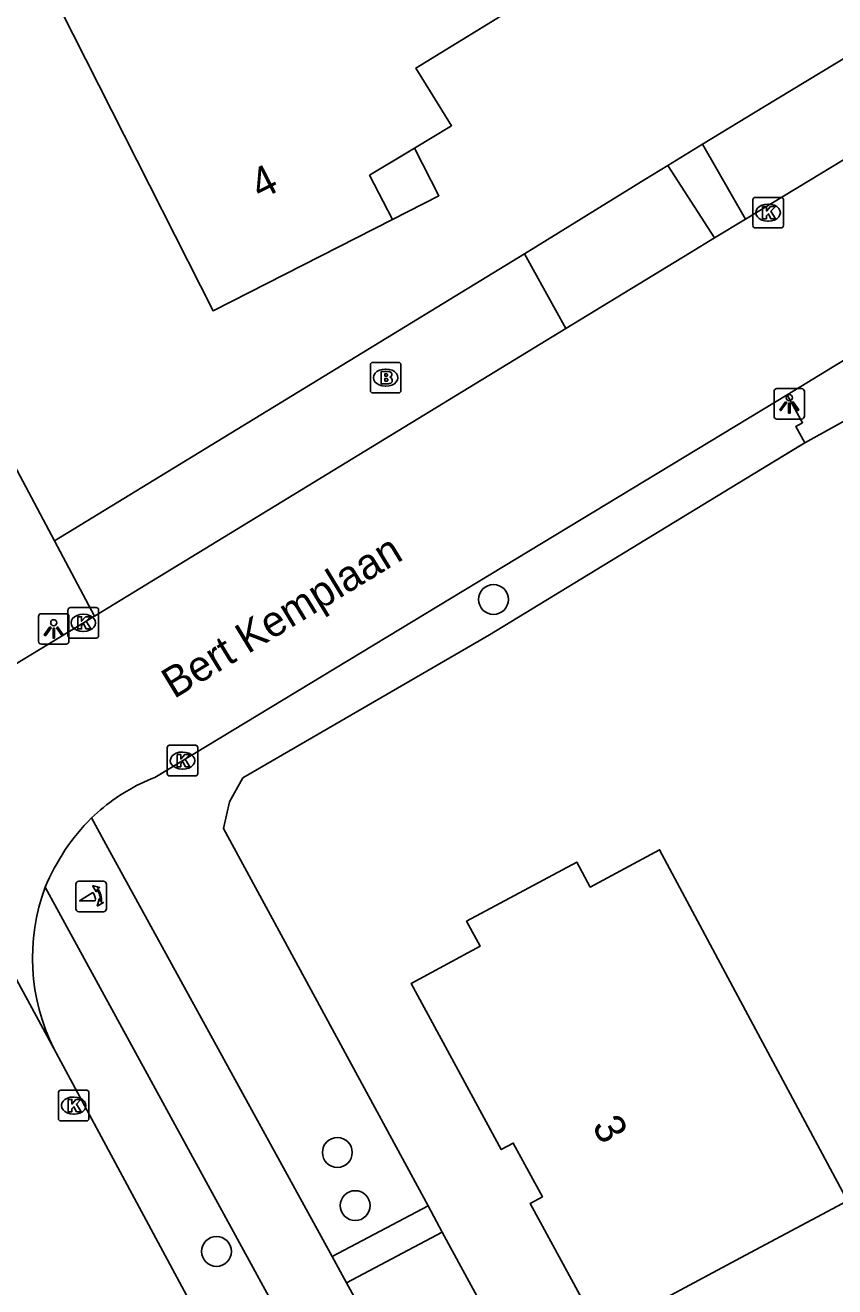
# Model space of a CAD drawing. Extents: x 157321 to 158827, y 386650 to 388532.
# Drawn here: x 157976.42 to 158002.92, y 387191.23 to 387232.53 of the extents above; entities that cross this region are included whole.
import ezdxf

# ---------------------------------------------------------------- set-up
doc = ezdxf.new("R2010")
doc.units = 0
for name, color, linetype in [('IMGEO_Boom', 7, 'Continuous'), ('IMGEO_Brandkraan', 7, 'Continuous'), ('IMGEO_Groenvoorziening', 7, 'Continuous'), ('IMGEO_Hek', 7, 'Continuous'), ('IMGEO_Kolk', 7, 'Continuous'), ('IMGEO_Lichtpunt', 7, 'Continuous'), ('IMGEO_Openbare_ruimte_label', 7, 'Continuous'), ('IMGEO_Pand', 7, 'Continuous'), ('IMGEO_Pand_nummerreeks', 7, 'Continuous'), ('IMGEO_Pand_overbouw', 7, 'Continuous'), ('IMGEO_Poller', 7, 'Continuous'), ('IMGEO_Rijbaan_lokaal_gesloten', 7, 'Continuous'), ('IMGEO_Voetpad_open', 7, 'Continuous')]:
    doc.layers.add(name, color=color, linetype=linetype)

msp = doc.modelspace()

# ---------------------------------------------------------------- linework, layer by layer
at = {"layer": 'IMGEO_Boom'}
for centre in [(157991.746, 387213.728), (157986.635, 387195.623), (157987.219, 387193.883), (157982.679, 387192.384)]:
    msp.add_circle(centre, 0.489, dxfattribs=at)
at = {"layer": 'IMGEO_Brandkraan'}
for p, q in [((157987.716, 387220.565), (157987.716, 387221.417)), ((157987.791, 387221.491), (157988.643, 387221.491)), ((157988.717, 387221.417), (157988.717, 387220.565)), ((157988.204, 387221.271), (157988.229, 387221.271)), ((157988.227, 387220.711), (157988.202, 387220.711)), ((157988.643, 387220.491), (157987.791, 387220.491))]:
    msp.add_line(p, q, dxfattribs=at)
for points in [[(157987.716, 387220.565), (157987.716, 387221.417)], [(157987.791, 387221.491), (157988.643, 387221.491)], [(157988.717, 387221.417), (157988.717, 387220.565)], [(157988.064, 387221.191), (157988.064, 387220.791), (157988.277, 387220.791)], [(157988.295, 387221.191), (157988.064, 387221.191)], [(157988.243, 387221.11), (157988.189, 387221.11), (157988.189, 387221.034)], [(157988.189, 387221.034), (157988.242, 387221.034)], [(157988.251, 387220.958), (157988.189, 387220.958), (157988.189, 387220.877)], [(157988.189, 387220.877), (157988.251, 387220.877)], [(157988.643, 387220.491), (157987.791, 387220.491)]]:
    msp.add_lwpolyline(points, dxfattribs=at)
for centre, radius, start, end in [((157987.793, 387221.415), 0.0765, 91.552, 178.448), ((157987.793, 387221.415), 0.0765, 91.552, 178.448), ((157988.641, 387221.415), 0.0765, 1.552, 88.448), ((157988.641, 387221.415), 0.0765, 1.552, 88.448), ((157988.244, 387221.072), 0.0379, 267.8285, 90.9355), ((157988.299, 387221.046), 0.145, 59.4692, 91.5367), ((157988.324, 387221.093), 0.0922, 285.5137, 58.1501), ((157988.329, 387220.901), 0.105, 301.3115, 78.989), ((157987.793, 387220.567), 0.0765, 181.552, 268.448), ((157987.793, 387220.567), 0.0765, 181.552, 268.448), ((157988.252, 387220.917), 0.0404, 269.8759, 90.5077), ((157988.283, 387221.042), 0.251, 268.6676, 293.5347), ((157988.641, 387220.567), 0.0765, 271.552, 358.448), ((157988.641, 387220.567), 0.0765, 271.552, 358.448)]:
    msp.add_arc(centre, radius, start, end, dxfattribs=at)
for centre, major_axis, ratio, start_param, end_param in [((157988.203, 387220.991), (-0.387, 0.002), 0.722429, 4.712389, 7.853982), ((157988.228, 387220.991), (-0.39, 0.002), 0.717154, 1.570796, 4.712389)]:
    msp.add_ellipse(centre, major_axis=major_axis, ratio=ratio, start_param=start_param, end_param=end_param, dxfattribs=at)
at = {"layer": 'IMGEO_Groenvoorziening'}
for points in [[(157963.282, 387242.2), (157977.374, 387215.649)], [(157997.452, 387227.935), (157998.588, 387228.631)], [(157977.374, 387215.649), (157992.758, 387225.048)], [(158001.936, 387218.855), (158000, 387217.682), (157991.613, 387212.573), (157983.543, 387207.885), (157983.105, 387207.103), (157982.905, 387206.23), (157989.606, 387193.874)], [(157977.374, 387215.649), (157978.682, 387213.184)], [(157990.07, 387193.018), (157992.639, 387188.28)]]:
    msp.add_lwpolyline(points, dxfattribs=at)
at = {"layer": 'IMGEO_Hek'}
for points in [[(158001.811, 387218.785), (158000, 387217.682)], [(158000, 387217.682), (157991.613, 387212.573)]]:
    msp.add_lwpolyline(points, dxfattribs=at)
at = {"layer": 'IMGEO_Kolk'}
for p, q in [((158000.235, 387225.966), (158000.235, 387226.818)), ((158000.31, 387226.892), (158001.162, 387226.892)), ((158001.236, 387226.818), (158001.236, 387225.966)), ((158000.723, 387226.672), (158000.748, 387226.672)), ((158000.746, 387226.112), (158000.721, 387226.112)), ((158001.162, 387225.892), (158000.31, 387225.892)), ((157977.818, 387212.538), (157977.818, 387213.39)), ((157977.893, 387213.464), (157978.745, 387213.464)), ((157978.306, 387213.244), (157978.331, 387213.244)), ((157978.819, 387213.39), (157978.819, 387212.538)), ((157978.745, 387212.464), (157977.893, 387212.464)), ((157978.329, 387212.684), (157978.304, 387212.684)), ((157981.066, 387208.027), (157981.066, 387208.879)), ((157981.141, 387208.953), (157981.993, 387208.953)), ((157981.554, 387208.733), (157981.579, 387208.733)), ((157982.067, 387208.879), (157982.067, 387208.027)), ((157981.577, 387208.173), (157981.552, 387208.173)), ((157981.993, 387207.953), (157981.141, 387207.953)), ((157977.504, 387196.732), (157977.504, 387197.584)), ((157977.579, 387197.658), (157978.431, 387197.658)), ((157977.992, 387197.438), (157978.017, 387197.438)), ((157978.505, 387197.584), (157978.505, 387196.732)), ((157978.431, 387196.658), (157977.579, 387196.658)), ((157978.015, 387196.878), (157977.99, 387196.878))]:
    msp.add_line(p, q, dxfattribs=at)
for points in [[(158000.235, 387225.966), (158000.235, 387226.818)], [(158000.31, 387226.892), (158001.162, 387226.892)], [(158001.236, 387226.818), (158001.236, 387225.966)], [(158000.556, 387226.592), (158000.679, 387226.592), (158000.679, 387226.441), (158000.809, 387226.592), (158000.973, 387226.592), (158000.827, 387226.441), (158000.98, 387226.192), (158000.828, 387226.192), (158000.743, 387226.356), (158000.679, 387226.289), (158000.679, 387226.192), (158000.556, 387226.192), (158000.556, 387226.592)], [(158001.162, 387225.892), (158000.31, 387225.892)], [(157977.818, 387212.538), (157977.818, 387213.39)], [(157977.893, 387213.464), (157978.745, 387213.464)], [(157978.139, 387213.164), (157978.262, 387213.164), (157978.262, 387213.013), (157978.392, 387213.164), (157978.556, 387213.164), (157978.41, 387213.013), (157978.563, 387212.764), (157978.411, 387212.764), (157978.326, 387212.928), (157978.262, 387212.861), (157978.262, 387212.764), (157978.139, 387212.764), (157978.139, 387213.164)], [(157978.819, 387213.39), (157978.819, 387212.538)], [(157978.745, 387212.464), (157977.893, 387212.464)], [(157981.066, 387208.027), (157981.066, 387208.879)], [(157981.141, 387208.953), (157981.993, 387208.953)], [(157981.387, 387208.653), (157981.51, 387208.653), (157981.51, 387208.502), (157981.64, 387208.653), (157981.804, 387208.653), (157981.658, 387208.502), (157981.811, 387208.253), (157981.659, 387208.253), (157981.574, 387208.417), (157981.51, 387208.35), (157981.51, 387208.253), (157981.387, 387208.253), (157981.387, 387208.653)], [(157982.067, 387208.879), (157982.067, 387208.027)], [(157981.993, 387207.953), (157981.141, 387207.953)], [(157977.504, 387196.732), (157977.504, 387197.584)], [(157977.579, 387197.658), (157978.431, 387197.658)], [(157978.505, 387197.584), (157978.505, 387196.732)], [(157977.825, 387197.358), (157977.948, 387197.358), (157977.948, 387197.207), (157978.078, 387197.358), (157978.242, 387197.358), (157978.096, 387197.207), (157978.249, 387196.958), (157978.097, 387196.958), (157978.012, 387197.122), (157977.948, 387197.055), (157977.948, 387196.958), (157977.825, 387196.958), (157977.825, 387197.358)], [(157978.431, 387196.658), (157977.579, 387196.658)]]:
    msp.add_lwpolyline(points, dxfattribs=at)
for centre, start, end in [((158000.312, 387226.816), 91.552, 178.448), ((158000.312, 387226.816), 91.552, 178.448), ((158001.16, 387226.816), 1.552, 88.448), ((158001.16, 387226.816), 1.552, 88.448), ((158000.312, 387225.968), 181.552, 268.448), ((158000.312, 387225.968), 181.552, 268.448), ((158001.16, 387225.968), 271.552, 358.448), ((158001.16, 387225.968), 271.552, 358.448), ((157977.895, 387213.388), 91.552, 178.448), ((157977.895, 387213.388), 91.552, 178.448), ((157978.743, 387213.388), 1.552, 88.448), ((157978.743, 387213.388), 1.552, 88.448), ((157977.895, 387212.54), 181.552, 268.448), ((157977.895, 387212.54), 181.552, 268.448), ((157978.743, 387212.54), 271.552, 358.448), ((157978.743, 387212.54), 271.552, 358.448), ((157981.143, 387208.877), 91.552, 178.448), ((157981.143, 387208.877), 91.552, 178.448), ((157981.991, 387208.877), 1.552, 88.448), ((157981.991, 387208.877), 1.552, 88.448), ((157981.143, 387208.029), 181.552, 268.448), ((157981.143, 387208.029), 181.552, 268.448), ((157981.991, 387208.029), 271.552, 358.448), ((157981.991, 387208.029), 271.552, 358.448), ((157977.581, 387197.582), 91.552, 178.448), ((157977.581, 387197.582), 91.552, 178.448), ((157978.429, 387197.582), 1.552, 88.448), ((157978.429, 387197.582), 1.552, 88.448), ((157977.581, 387196.734), 181.552, 268.448), ((157977.581, 387196.734), 181.552, 268.448), ((157978.429, 387196.734), 271.552, 358.448), ((157978.429, 387196.734), 271.552, 358.448)]:
    msp.add_arc(centre, 0.0765, start, end, dxfattribs=at)
for centre, major_axis, ratio, start_param, end_param in [((158000.722, 387226.392), (-0.387, 0.002), 0.722429, 4.712389, 7.853982), ((158000.747, 387226.392), (-0.39, 0.002), 0.717154, 1.570796, 4.712389), ((157978.305, 387212.964), (-0.387, 0.002), 0.722429, 4.712389, 7.853982), ((157978.33, 387212.964), (-0.39, 0.002), 0.717154, 1.570796, 4.712389), ((157981.553, 387208.453), (-0.387, 0.002), 0.722429, 4.712389, 7.853982), ((157981.578, 387208.453), (-0.39, 0.002), 0.717154, 1.570796, 4.712389), ((157977.991, 387197.158), (-0.387, 0.002), 0.722429, 4.712389, 7.853982), ((157978.016, 387197.158), (-0.39, 0.002), 0.717154, 1.570796, 4.712389)]:
    msp.add_ellipse(centre, major_axis=major_axis, ratio=ratio, start_param=start_param, end_param=end_param, dxfattribs=at)
at = {"layer": 'IMGEO_Lichtpunt'}
for p, q in [((158001.832, 387220.631), (158001.024, 387220.631)), ((158001.832, 387220.631), (158001.024, 387220.631)), ((158000.93, 387220.536), (158000.93, 387219.729)), ((158000.93, 387220.536), (158000.93, 387219.729)), ((158001.926, 387219.729), (158001.926, 387220.536)), ((158001.926, 387219.729), (158001.926, 387220.536)), ((158001.024, 387219.635), (158001.832, 387219.635)), ((158001.024, 387219.635), (158001.832, 387219.635)), ((157976.852, 387213.168), (157976.852, 387212.361)), ((157976.852, 387213.168), (157976.852, 387212.361)), ((157977.754, 387213.263), (157976.946, 387213.263)), ((157977.754, 387213.263), (157976.946, 387213.263)), ((157977.848, 387212.361), (157977.848, 387213.168)), ((157977.848, 387212.361), (157977.848, 387213.168)), ((157976.946, 387212.267), (157977.754, 387212.267)), ((157976.946, 387212.267), (157977.754, 387212.267))]:
    msp.add_line(p, q, dxfattribs=at)
for points in [[(158001.304, 387220.2), (158001.343, 387220.172), (158001.155, 387219.91), (158001.117, 387219.937), (158001.304, 387220.2)], [(158001.406, 387220.152), (158001.453, 387220.152), (158001.453, 387219.83), (158001.406, 387219.83), (158001.406, 387220.152)], [(158001.516, 387220.172), (158001.554, 387220.199), (158001.741, 387219.937), (158001.702, 387219.909), (158001.516, 387220.172)], [(157977.226, 387212.832), (157977.265, 387212.804), (157977.077, 387212.542), (157977.039, 387212.569), (157977.226, 387212.832)], [(157977.328, 387212.784), (157977.375, 387212.784), (157977.375, 387212.462), (157977.328, 387212.462), (157977.328, 387212.784)], [(157977.438, 387212.804), (157977.476, 387212.831), (157977.663, 387212.569), (157977.624, 387212.541), (157977.438, 387212.804)]]:
    msp.add_lwpolyline(points, dxfattribs=at)
for centre in [(158001.429, 387220.334), (157977.351, 387212.966)]:
    msp.add_circle(centre, 0.0994, dxfattribs=at)
for centre, start, end in [((158001.024, 387220.536), 90, 180), ((158001.024, 387220.536), 90, 180), ((158001.832, 387220.536), 0, 90), ((158001.832, 387220.536), 0, 90), ((158001.024, 387219.729), 180, 270), ((158001.024, 387219.729), 180, 270), ((158001.832, 387219.729), 270, 0), ((158001.832, 387219.729), 270, 360), ((157976.946, 387213.168), 90, 180), ((157976.946, 387213.168), 90, 180), ((157977.754, 387213.168), 0, 90), ((157977.754, 387213.168), 0, 90), ((157976.946, 387212.361), 180, 270), ((157976.946, 387212.361), 180, 270), ((157977.754, 387212.361), 270, 0), ((157977.754, 387212.361), 270, 360)]:
    msp.add_arc(centre, 0.0946, start, end, dxfattribs=at)
at = {"layer": 'IMGEO_Pand'}
for points in [[(157980.561, 387250.026), (157983.812, 387244.787), (157981.75, 387243.508), (157984.461, 387238.183), (157982.503, 387237.186), (157982.751, 387236.695), (157977.156, 387233.869), (157982.567, 387223.182), (157988.436, 387226.169), (157987.692, 387227.619), (157988.912, 387228.355), (157989.156, 387228.502), (157990.376, 387229.238), (157989.74, 387230.264), (157989.206, 387231.125), (157993.496, 387233.759), (157994.017, 387232.917), (157994.365, 387233.133), (157984.044, 387250), (157983.087, 387251.564), (157983.035, 387251.532)], [(158000, 387200.268), (158003.33, 387194.04), (158000, 387192.26), (157995.244, 387189.717), (157992.951, 387193.957), (157993.347, 387194.172), (157992.395, 387195.931), (157991.999, 387195.716), (157989.054, 387201.158), (157991.306, 387202.376), (157990.865, 387203.191), (157994.47, 387205.13), (157994.911, 387204.314), (157997.185, 387205.533), (158000, 387200.268)]]:
    msp.add_lwpolyline(points, dxfattribs=at)
at = {"layer": 'IMGEO_Pand_overbouw'}
msp.add_lwpolyline([(157989.156, 387228.502), (157987.692, 387227.619), (157988.436, 387226.169), (157989.959, 387226.944)], close=True, dxfattribs=at)
at = {"layer": 'IMGEO_Poller'}
for p, q in [((157978.979, 387204.502), (157978.171, 387204.502)), ((157978.979, 387204.502), (157978.171, 387204.502)), ((157978.077, 387204.407), (157978.077, 387203.6)), ((157978.077, 387204.407), (157978.077, 387203.6)), ((157979.073, 387203.6), (157979.073, 387204.407)), ((157979.073, 387203.6), (157979.073, 387204.407)), ((157978.171, 387203.505), (157978.979, 387203.505)), ((157978.171, 387203.505), (157978.979, 387203.505))]:
    msp.add_line(p, q, dxfattribs=at)
for points in [[(157978.712, 387203.858), (157978.199, 387203.858), (157978.629, 387204.133)], [(157978.756, 387204.231), (157978.744, 387204.158), (157978.619, 387204.363)], [(157978.619, 387204.363), (157978.85, 387204.297), (157978.779, 387204.265)], [(157978.772, 387203.686), (157978.838, 387203.917), (157978.868, 387203.849)], [(157978.904, 387203.822), (157978.976, 387203.811), (157978.772, 387203.686)]]:
    msp.add_lwpolyline(points, dxfattribs=at)
for centre, radius, start, end in [((157978.171, 387204.407), 0.0946, 90, 180), ((157978.171, 387204.407), 0.0946, 90, 180), ((157978.979, 387204.407), 0.0946, 0, 90), ((157978.979, 387204.407), 0.0946, 0, 90), ((157978.384, 387203.908), 0.332, 351.3247, 42.4854), ((157978.398, 387203.918), 0.476, 351.7527, 41.1691), ((157978.398, 387203.918), 0.516, 349.3569, 42.2912), ((157978.171, 387203.6), 0.0946, 180, 270), ((157978.171, 387203.6), 0.0946, 180, 270), ((157978.979, 387203.6), 0.0946, 270, 0), ((157978.979, 387203.6), 0.0946, 270, 0)]:
    msp.add_arc(centre, radius, start, end, dxfattribs=at)
at = {"layer": 'IMGEO_Rijbaan_lokaal_gesloten'}
for points in [[(158000, 387226.184), (158002.063, 387227.435), (158005.773, 387229.685)], [(157998.983, 387225.567), (158000, 387226.184)], [(157994.11, 387222.595), (157998.159, 387225.068), (157998.983, 387225.567)], [(158007.352, 387224.083), (158001.355, 387220.426)], [(157978.682, 387213.184), (157994.11, 387222.595)], [(158001.355, 387220.426), (157980.657, 387207.902)], [(157976.05, 387211.578), (157978.682, 387213.184)], [(157971.902, 387209.086), (157977.357, 387199.024)], [(157978.88, 387206.838), (157978.589, 387206.575)], [(157977.357, 387199.024), (157986.504, 387182.006)]]:
    msp.add_lwpolyline(points, dxfattribs=at)
for centre, radius, start, end in [((157983.022, 387201.937), 6.417, 111.6239, 130.1993), ((157983.557, 387201.605), 7.027, 134.988, 157.3874), ((157983.324, 387201.997), 6.667, 159.732, 206.4871)]:
    msp.add_arc(centre, radius, start, end, dxfattribs=at)
at = {"layer": 'IMGEO_Voetpad_open'}
for points in [[(157998.588, 387228.631), (158000.612, 387229.872), (158004.318, 387232.11)], [(157998.588, 387228.631), (158000, 387226.184)], [(157992.758, 387225.048), (157996.704, 387227.477), (157997.452, 387227.935)], [(157997.452, 387227.935), (157998.983, 387225.567)], [(157992.758, 387225.048), (157994.11, 387222.595)], [(158008.21, 387222.708), (158003.847, 387219.918), (158001.936, 387218.855)], [(158001.355, 387220.426), (158001.862, 387219.516), (158001.638, 387219.391), (158001.936, 387218.855)], [(157978.589, 387206.575), (157979.19, 387205.479), (157986.461, 387192.214)], [(157988.575, 387183.262), (157977.07, 387204.307)], [(157986.461, 387192.214), (157989.606, 387193.874)], [(157989.606, 387193.874), (157990.07, 387193.018)], [(157990.07, 387193.018), (157986.933, 387191.352)], [(157986.933, 387191.352), (157986.461, 387192.214)], [(157986.933, 387191.352), (157989.539, 387186.599)]]:
    msp.add_lwpolyline(points, dxfattribs=at)

# ---------------------------------------------------------------- texts
at = {"layer": 'IMGEO_Openbare_ruimte_label'}
msp.add_text('Bert Kemplaan', height=1, rotation=31.3372, dxfattribs=at).set_placement((157981.289, 387210.46))
at = {"layer": 'IMGEO_Pand_nummerreeks'}
for s, rotation, p in [('4', 26.9749, (157984.113, 387226.796)), ('3', 298.423, (157994.956, 387196.493))]:
    msp.add_text(s, height=1, rotation=rotation, dxfattribs=at).set_placement(p)

doc.saveas('drawing.dxf')
